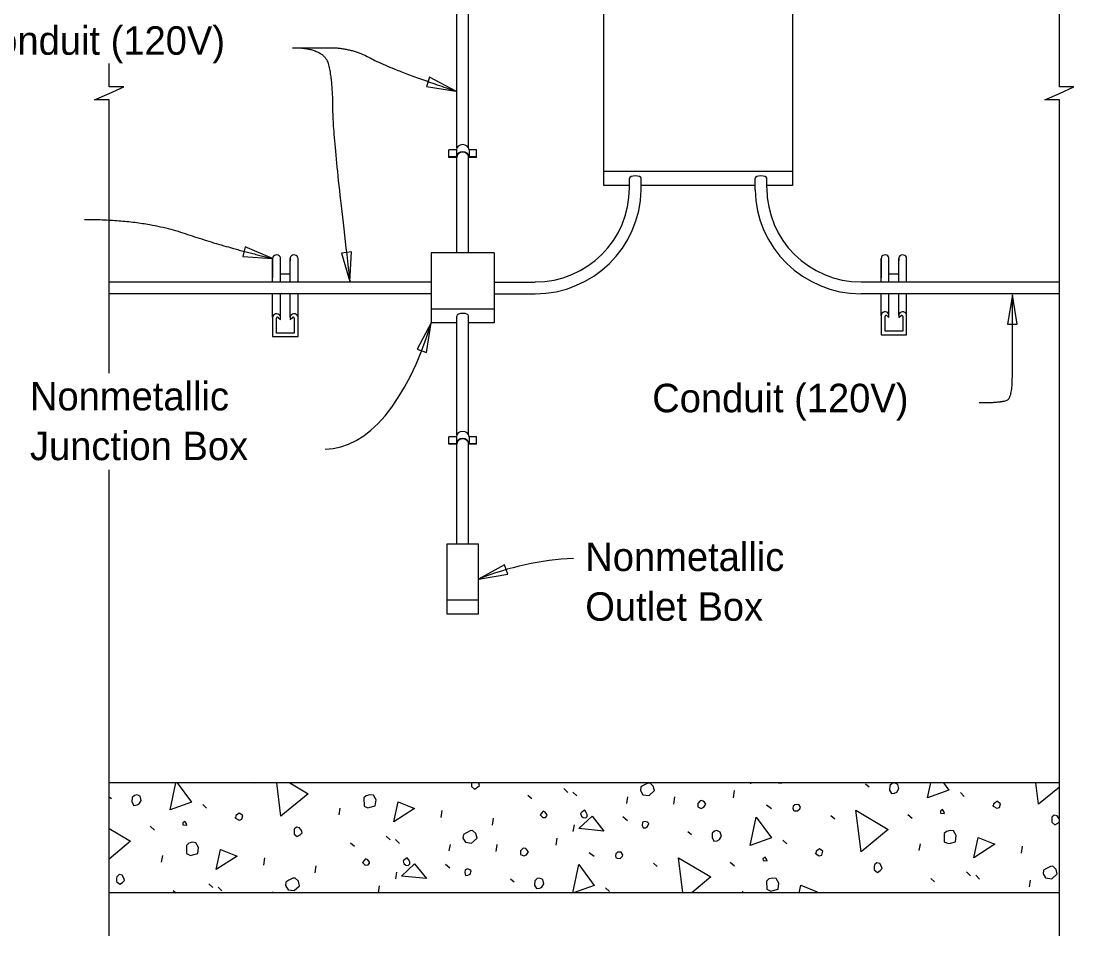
# Model space of a CAD drawing. Extents: x 112544 to 112597.1, y 111084 to 111107.1.
# Drawn here: x 112556.46 to 112562.05, y 111095.87 to 111100.72 of the extents above; entities that cross this region are included whole.
import ezdxf

# ---------------------------------------------------------------- set-up
doc = ezdxf.new("R2010")
doc.units = 0
for name, color, linetype in [('Dimension', 7, 'Continuous'), ('Lighting', 7, 'Continuous'), ('Miscellaneous', 7, 'Continuous'), ('SteelGirder', 7, 'Continuous'), ('SupstrConc', 7, 'Continuous'), ('TextStructures', 7, 'Continuous')]:
    doc.layers.add(name, color=color, linetype=linetype)

msp = doc.modelspace()

# ---------------------------------------------------------------- linework, layer by layer
at = {"layer": 'Dimension'}
for points in [[(112561.9699, 111095.8655), (112561.9699, 111100.3037), (112561.8924, 111100.3037), (112561.9699, 111100.3375), (112562.0474, 111100.3712), (112561.9699, 111100.3712), (112561.9699, 111101.4759)], [(112556.9271, 111098.8519), (112556.9271, 111100.3037), (112556.8496, 111100.3037), (112556.9271, 111100.3375), (112557.0046, 111100.3712), (112556.9271, 111100.3712), (112556.9271, 111100.4962)], [(112556.9271, 111095.8655), (112556.9271, 111098.3401)]]:
    msp.add_lwpolyline(points, dxfattribs=at)
for points in [[(112558.7675, 111100.3488), (112558.628, 111100.424), (112558.6111, 111100.3738)], [(112557.7946, 111099.4611), (112557.6487, 111099.5227), (112557.6365, 111099.4712)], [(112558.2053, 111099.3383), (112558.2127, 111099.4965), (112558.1602, 111099.4901)], [(112561.7205, 111099.2686), (112561.694, 111099.1124), (112561.7469, 111099.1124)], [(112558.637, 111099.1186), (112558.5614, 111098.9794), (112558.6114, 111098.9623)], [(112558.8871, 111097.7595), (112559.0433, 111097.7855), (112559.0261, 111097.8356)]]:
    msp.add_lwpolyline(points, close=True, dxfattribs=at)
msp.add_arc((112559.4765, 111096.2657), 1.606, 93.0575, 111.5329, dxfattribs=at)
msp.add_ellipse((112558.0721, 111100.0271), major_axis=(-0.0019, 1.5782), ratio=0.437101, start_param=3.141566, end_param=4.098452, dxfattribs=at)
for points in [[(112557.9001, 111100.5798), (112557.9837, 111100.5798), (112558.2136, 111100.5798), (112558.4185, 111100.4669), (112558.7675, 111100.3488)], [(112557.9001, 111100.5798), (112558.0715, 111100.5798), (112558.1133, 111100.3959), (112558.1133, 111100.0949), (112558.2053, 111099.3383)], [(112556.7965, 111099.6685), (112557.1101, 111099.6685), (112557.549, 111099.5191), (112557.7946, 111099.4611)], [(112561.5444, 111098.6959), (112561.6709, 111098.6959), (112561.7205, 111098.7257), (112561.7205, 111098.9513), (112561.7205, 111099.2686)]]:
    msp.add_open_spline(points, degree=2, dxfattribs=at)
at = {"layer": 'Lighting'}
for p, q in [((112558.7725, 111100.0474), (112558.7725, 111100.811)), ((112558.8349, 111100.0474), (112558.8349, 111100.811)), ((112558.7725, 111099.4913), (112558.7725, 111099.9976)), ((112558.8349, 111099.4913), (112558.8349, 111099.9976)), ((112560.5529, 111099.9227), (112559.5529, 111099.9227)), ((112559.6884, 111099.8362), (112559.6884, 111099.8856)), ((112559.7508, 111099.8256), (112559.7508, 111099.8856)), ((112560.355, 111099.8256), (112560.355, 111099.8856)), ((112560.4174, 111099.8362), (112560.4174, 111099.8856)), ((112558.637, 111099.4913), (112558.637, 111099.1186)), ((112558.9704, 111099.4913), (112558.637, 111099.4913)), ((112558.9704, 111099.4913), (112558.9704, 111099.1186)), ((112557.7946, 111099.3361), (112557.7946, 111099.4611)), ((112557.7946, 111099.4611), (112557.7946, 111099.3586)), ((112557.8362, 111099.4655), (112557.8341, 111099.4693)), ((112557.8362, 111099.4494), (112557.8362, 111099.4655)), ((112557.8362, 111099.3361), (112557.8362, 111099.4611)), ((112557.8905, 111099.4693), (112557.8884, 111099.4655)), ((112557.8884, 111099.4655), (112557.8884, 111099.4494)), ((112557.8884, 111099.3361), (112557.8884, 111099.4611)), ((112557.93, 111099.3361), (112557.93, 111099.4611)), ((112561.0242, 111099.3361), (112561.0242, 111099.4611)), ((112561.0242, 111099.4611), (112561.0242, 111099.3586)), ((112561.0658, 111099.4655), (112561.0636, 111099.4693)), ((112561.0658, 111099.4494), (112561.0658, 111099.4655)), ((112561.0658, 111099.3361), (112561.0658, 111099.4611)), ((112561.1201, 111099.4693), (112561.118, 111099.4655)), ((112561.118, 111099.4655), (112561.118, 111099.4494)), ((112561.118, 111099.3361), (112561.118, 111099.4611)), ((112561.1596, 111099.3361), (112561.1596, 111099.4611)), ((112557.8884, 111099.3772), (112557.8362, 111099.3772)), ((112561.118, 111099.3772), (112561.0658, 111099.3772)), ((112558.637, 111099.3361), (112556.9271, 111099.3361)), ((112558.9704, 111099.3361), (112559.1884, 111099.3361)), ((112561.9699, 111099.3361), (112560.9174, 111099.3361)), ((112558.637, 111099.2737), (112556.9271, 111099.2737)), ((112557.7946, 111099.1487), (112557.7946, 111099.2737)), ((112557.8362, 111099.1487), (112557.8362, 111099.2737)), ((112557.8884, 111099.1487), (112557.8884, 111099.2737)), ((112557.93, 111099.1487), (112557.93, 111099.2737)), ((112558.9704, 111099.2737), (112559.1884, 111099.2737)), ((112561.9699, 111099.2737), (112560.9174, 111099.2737)), ((112561.0242, 111099.159), (112561.0242, 111099.2737)), ((112561.0658, 111099.159), (112561.0658, 111099.2737)), ((112561.118, 111099.159), (112561.118, 111099.2737)), ((112561.1596, 111099.159), (112561.1596, 111099.2737)), ((112557.7946, 111099.1487), (112557.7946, 111099.0462)), ((112557.8154, 111099.0648), (112557.8154, 111099.1444)), ((112557.8243, 111099.1477), (112557.8362, 111099.137)), ((112557.8362, 111099.1531), (112557.8341, 111099.1569)), ((112557.8362, 111099.137), (112557.8362, 111099.1531)), ((112557.8905, 111099.1569), (112557.8884, 111099.1531)), ((112557.8884, 111099.1531), (112557.8884, 111099.137)), ((112557.8884, 111099.137), (112557.9003, 111099.1477)), ((112557.9092, 111099.1444), (112557.9092, 111099.0648)), ((112557.93, 111099.0462), (112557.93, 111099.1487)), ((112558.9704, 111099.1928), (112558.637, 111099.1928)), ((112558.7725, 111098.5253), (112558.7725, 111099.1557)), ((112558.8349, 111098.5253), (112558.8349, 111099.1557)), ((112561.0242, 111099.159), (112561.0242, 111099.0565)), ((112561.045, 111099.0751), (112561.045, 111099.1547)), ((112561.0539, 111099.158), (112561.0658, 111099.1473)), ((112561.0658, 111099.1634), (112561.0636, 111099.1672)), ((112561.0658, 111099.1473), (112561.0658, 111099.1634)), ((112561.1201, 111099.1672), (112561.118, 111099.1634)), ((112561.118, 111099.1634), (112561.118, 111099.1473)), ((112561.118, 111099.1473), (112561.1299, 111099.158)), ((112561.1388, 111099.1547), (112561.1388, 111099.0751)), ((112561.1596, 111099.0565), (112561.1596, 111099.159)), ((112558.7725, 111099.1186), (112558.637, 111099.1186)), ((112558.9704, 111099.1186), (112558.8349, 111099.1186)), ((112557.7946, 111099.0462), (112557.93, 111099.0462)), ((112557.9092, 111099.0648), (112557.8154, 111099.0648)), ((112561.0242, 111099.0565), (112561.1596, 111099.0565)), ((112561.1388, 111099.0751), (112561.045, 111099.0751)), ((112558.7725, 111097.9459), (112558.7725, 111098.4755)), ((112558.8349, 111097.9459), (112558.8349, 111098.4755)), ((112558.7204, 111097.5733), (112558.7204, 111097.9459)), ((112558.7204, 111097.9459), (112558.887, 111097.9459)), ((112558.887, 111097.5733), (112558.887, 111097.9459)), ((112558.887, 111097.6476), (112558.7204, 111097.6476)), ((112558.887, 111097.5733), (112558.7204, 111097.5733))]:
    msp.add_line(p, q, dxfattribs=at)
for points in [[(112559.6884, 111099.8484), (112559.5529, 111099.8484), (112559.5529, 111102.5734), (112560.5529, 111102.5734), (112560.5529, 111099.8484), (112560.4174, 111099.8484)], [(112560.355, 111099.8484), (112559.7507, 111099.8484)]]:
    msp.add_lwpolyline(points, dxfattribs=at)
for centre, radius, start, end in [((112559.1884, 111099.8362), 0.5, 270, 0), ((112559.1884, 111099.8362), 0.5625, 270, 358.9196), ((112560.9174, 111099.8362), 0.5625, 181.0804, 270), ((112560.9174, 111099.8362), 0.5, 180, 270)]:
    msp.add_arc(centre, radius, start, end, dxfattribs=at)
for centre, major_axis, ratio, start_param, end_param in [((112559.7196, 111099.8856), (-0.0312, 0), 0.446008, 3.14248, 6.283159), ((112560.3862, 111099.8856), (-0.0312, 0), 0.446008, 3.141619, 6.282298), ((112557.8154, 111099.4611), (-0.0208, 0), 0.8951, 3.598509, 6.283184), ((112557.9092, 111099.4611), (0.0208, 0), 0.8951, 0.000002, 2.684677), ((112561.045, 111099.4611), (-0.0208, 0), 0.8951, 3.598509, 6.283184), ((112561.1388, 111099.4611), (0.0208, 0), 0.8951, 0.000002, 2.684677), ((112557.8154, 111099.1487), (-0.0208, 0), 0.8951, 3.598509, 6.283184), ((112557.8206, 111099.1444), (-0.0052, 0), 0.8951, 3.926991, 6.283185), ((112557.9092, 111099.1487), (0.0208, 0), 0.8951, 0.000002, 2.684677), ((112557.904, 111099.1444), (0.0052, 0), 0.8951, 6.283185, 8.63938), ((112558.8037, 111099.1557), (-0.0312, 0), 0.446008, 3.14248, 6.283159), ((112561.045, 111099.159), (-0.0208, 0), 0.8951, 3.598509, 6.283184), ((112561.0502, 111099.1547), (-0.0052, 0), 0.8951, 3.926991, 6.283185), ((112561.1388, 111099.159), (0.0208, 0), 0.8951, 0.000002, 2.684677), ((112561.1336, 111099.1547), (0.0052, 0), 0.8951, 6.283185, 8.63938)]:
    msp.add_ellipse(centre, major_axis=major_axis, ratio=ratio, start_param=start_param, end_param=end_param, dxfattribs=at)
at = {"layer": 'Miscellaneous'}
for p, q in [((112557.6971, 111096.6779), (112557.6991, 111096.6762)), ((112559.3399, 111096.6474), (112559.3609, 111096.6272)), ((112559.3887, 111096.6294), (112559.4097, 111096.6092)), ((112560.2407, 111096.5989), (112560.2461, 111096.6366)), ((112560.3322, 111096.6726), (112560.3331, 111096.6779)), ((112560.9405, 111096.6725), (112560.9601, 111096.6571)), ((112556.9271, 111096.6039), (112556.9394, 111096.5943)), ((112559.1501, 111096.6121), (112559.1704, 111096.5942)), ((112559.6742, 111096.5688), (112559.6803, 111096.604)), ((112559.9235, 111096.5657), (112559.9289, 111096.6034)), ((112561.4446, 111096.6264), (112561.4655, 111096.6062)), ((112557.4238, 111096.5636), (112557.4448, 111096.5434)), ((112558.1476, 111096.5091), (112558.1537, 111096.5444)), ((112558.69, 111096.494), (112558.6954, 111096.5317)), ((112560.4166, 111096.5606), (112560.4424, 111096.5417)), ((112558.9624, 111096.4531), (112558.9678, 111096.4908)), ((112559.6541, 111096.4987), (112559.6775, 111096.4791)), ((112560.7577, 111096.5045), (112560.778, 111096.4867)), ((112561.1652, 111096.5101), (112561.1885, 111096.4905)), ((112557.1444, 111096.4474), (112557.1678, 111096.4277)), ((112559.3904, 111096.4203), (112559.3965, 111096.4555)), ((112559.9987, 111096.4202), (112560.0184, 111096.4047)), ((112558.2083, 111096.3597), (112558.2286, 111096.3419)), ((112558.3982, 111096.3951), (112558.4191, 111096.3748)), ((112558.447, 111096.3771), (112558.4679, 111096.3568)), ((112558.7324, 111096.3164), (112558.7385, 111096.3517)), ((112558.9817, 111096.3133), (112558.9871, 111096.351)), ((112559.2989, 111096.3466), (112559.3043, 111096.3842)), ((112560.5028, 111096.3741), (112560.5238, 111096.3538)), ((112561.2266, 111096.3196), (112561.2327, 111096.3548)), ((112557.2058, 111096.2568), (112557.2119, 111096.292)), ((112559.4748, 111096.3083), (112559.5006, 111096.2893)), ((112561.769, 111096.3044), (112561.7744, 111096.3421)), ((112557.7482, 111096.2416), (112557.7536, 111096.2793)), ((112558.0206, 111096.2007), (112558.026, 111096.2384)), ((112558.7124, 111096.2463), (112558.7357, 111096.2267)), ((112559.816, 111096.2522), (112559.8363, 111096.2343)), ((112560.2234, 111096.2578), (112560.2467, 111096.2382)), ((112558.4487, 111096.1679), (112558.4547, 111096.2032)), ((112561.4771, 111096.2055), (112561.4981, 111096.1852)), ((112561.5259, 111096.1875), (112561.5469, 111096.1673)), ((112557.4564, 111096.1427), (112557.4773, 111096.1225)), ((112557.5052, 111096.1247), (112557.5261, 111096.1045)), ((112558.3572, 111096.0946), (112558.3626, 111096.1319)), ((112559.0569, 111096.1678), (112559.0766, 111096.1524)), ((112561.2873, 111096.1702), (112561.3076, 111096.1523)), ((112561.8114, 111096.1268), (112561.8175, 111096.1621)), ((112557.2666, 111096.1074), (112557.2811, 111096.0946)), ((112557.7959, 111096.0946), (112557.7967, 111096.0993)), ((112558.0448, 111096.0946), (112558.0453, 111096.0987)), ((112559.561, 111096.1217), (112559.582, 111096.1015)), ((112560.2895, 111096.0946), (112560.2909, 111096.1025))]:
    msp.add_line(p, q, dxfattribs=at)
for points in [[(112557.2503, 111096.5353), (112557.2805, 111096.6779)], [(112557.2884, 111096.6779), (112557.3636, 111096.576), (112557.2503, 111096.5353)], [(112557.8391, 111096.5015), (112557.8167, 111096.6779)], [(112557.8855, 111096.6779), (112557.9832, 111096.6204), (112557.8391, 111096.5015)], [(112558.8507, 111096.6768), (112558.8504, 111096.6586), (112558.867, 111096.6449), (112558.8826, 111096.6543), (112558.8927, 111096.6648), (112558.8895, 111096.6768), (112558.8888, 111096.6779)], [(112558.8507, 111096.6779), (112558.8507, 111096.6768)], [(112559.7464, 111096.6373), (112559.7601, 111096.6151), (112559.7923, 111096.6108), (112559.8216, 111096.6367), (112559.8151, 111096.6609), (112559.7979, 111096.677), (112559.7852, 111096.6761), (112559.7647, 111096.6655), (112559.7491, 111096.6561), (112559.7464, 111096.6373)], [(112560.4922, 111096.6779), (112560.4947, 111096.6747), (112560.4632, 111096.6779)], [(112561.0698, 111096.6632), (112561.0684, 111096.6395), (112561.0784, 111096.6215), (112561.0959, 111096.6236), (112561.1074, 111096.6292), (112561.118, 111096.6476), (112561.1121, 111096.6694), (112561.0944, 111096.6775), (112561.0823, 111096.6743), (112561.0698, 111096.6632)], [(112561.271, 111096.598), (112561.288, 111096.6779)], [(112561.3554, 111096.6779), (112561.3843, 111096.6388), (112561.271, 111096.598)], [(112561.8598, 111096.5643), (112561.8454, 111096.6779)], [(112561.9699, 111096.655), (112561.8598, 111096.5643)], [(112557.049, 111096.6004), (112557.0476, 111096.5767), (112557.0576, 111096.5587), (112557.0752, 111096.5608), (112557.0866, 111096.5665), (112557.0972, 111096.5848), (112557.0914, 111096.6066), (112557.0737, 111096.6148), (112557.0616, 111096.6115), (112557.049, 111096.6004)], [(112558.2789, 111096.5986), (112558.2802, 111096.555), (112558.301, 111096.545), (112558.3131, 111096.5483), (112558.3397, 111096.5554), (112558.344, 111096.5876), (112558.3296, 111096.6122), (112558.3108, 111096.615), (112558.2914, 111096.6098), (112558.2789, 111096.5986)], [(112558.4375, 111096.4703), (112558.4606, 111096.5774), (112558.5479, 111096.5413), (112558.4375, 111096.4703)], [(112560.052, 111096.569), (112560.0517, 111096.5508), (112560.0694, 111096.5427), (112560.0832, 111096.549), (112560.0945, 111096.5649), (112560.0864, 111096.5757), (112560.0797, 111096.5816), (112560.0687, 111096.5839), (112560.0639, 111096.5826), (112560.052, 111096.569)], [(112561.6192, 111096.5542), (112561.6376, 111096.5436), (112561.6521, 111096.5474), (112561.6572, 111096.5669), (112561.6382, 111096.58), (112561.6298, 111096.5725), (112561.6208, 111096.5675), (112561.6192, 111096.5542), (112561.6179, 111096.559)], [(112557.5985, 111096.4914), (112557.6168, 111096.4808), (112557.6313, 111096.4847), (112557.6365, 111096.5042), (112557.6174, 111096.5172), (112557.6091, 111096.5098), (112557.6001, 111096.5048), (112557.5985, 111096.4914), (112557.5972, 111096.4962)], [(112559.2143, 111096.5077), (112559.2285, 111096.4933), (112559.2436, 111096.4948), (112559.2514, 111096.5046), (112559.2501, 111096.5095), (112559.2414, 111096.5227), (112559.2298, 111096.5273), (112559.222, 111096.5175), (112559.2143, 111096.5077)], [(112559.4333, 111096.5016), (112559.4432, 111096.4939), (112559.4565, 111096.4923), (112559.4649, 111096.4997), (112559.4647, 111096.51), (112559.4591, 111096.5215), (112559.451, 111096.5323), (112559.4378, 111096.5235), (112559.4295, 111096.5161), (112559.4333, 111096.5016)], [(112560.5583, 111096.5339), (112560.5645, 111096.5304), (112560.5802, 111096.5294), (112560.5928, 111096.5405), (112560.5957, 111096.5491), (112560.587, 111096.5623), (112560.5663, 111096.5619), (112560.558, 111096.5545), (112560.5557, 111096.5436), (112560.5583, 111096.5339)], [(112560.918, 111096.3119), (112560.8901, 111096.5322), (112561.0622, 111096.4308), (112560.918, 111096.3119)], [(112561.3391, 111096.5179), (112561.3603, 111096.5159), (112561.3577, 111096.5255), (112561.3497, 111096.5363), (112561.3389, 111096.5282), (112561.3391, 111096.5179)], [(112557.3183, 111096.4551), (112557.3396, 111096.4531), (112557.337, 111096.4627), (112557.3289, 111096.4735), (112557.3181, 111096.4654), (112557.3183, 111096.4551)], [(112559.4199, 111096.4359), (112559.4904, 111096.5014), (112559.5529, 111096.4224), (112559.4199, 111096.4359)], [(112559.7568, 111096.4537), (112559.7607, 111096.4392), (112559.7734, 111096.44), (112559.7848, 111096.4457), (112559.7906, 111096.4628), (112559.7838, 111096.4687), (112559.7722, 111096.4734), (112559.7577, 111096.4695), (112559.7568, 111096.4537)], [(112560.3292, 111096.3457), (112560.3613, 111096.4966), (112560.4426, 111096.3864), (112560.3292, 111096.3457)], [(112561.9296, 111096.4872), (112561.9293, 111096.469), (112561.9459, 111096.4554), (112561.9615, 111096.4647), (112561.9699, 111096.4733)], [(112561.9699, 111096.482), (112561.9684, 111096.4873), (112561.9591, 111096.5029), (112561.9427, 111096.5062), (112561.9301, 111096.4951), (112561.9296, 111096.4872)], [(112556.9271, 111096.4354), (112557.0414, 111096.368), (112556.9271, 111096.2738)], [(112557.9089, 111096.4244), (112557.9086, 111096.4062), (112557.9252, 111096.3926), (112557.9408, 111096.4019), (112557.9509, 111096.4124), (112557.9477, 111096.4245), (112557.9383, 111096.4401), (112557.9219, 111096.4435), (112557.9094, 111096.4323), (112557.9089, 111096.4244)], [(112558.8046, 111096.3849), (112558.8183, 111096.3627), (112558.8506, 111096.3584), (112558.8798, 111096.3844), (112558.8734, 111096.4085), (112558.8561, 111096.4246), (112558.8434, 111096.4238), (112558.823, 111096.4131), (112558.8073, 111096.4038), (112558.8046, 111096.3849)], [(112560.128, 111096.4108), (112560.1266, 111096.3872), (112560.1366, 111096.3691), (112560.1542, 111096.3712), (112560.1656, 111096.3769), (112560.1762, 111096.3953), (112560.1704, 111096.417), (112560.1526, 111096.4252), (112560.1406, 111096.422), (112560.128, 111096.4108)], [(112561.3579, 111096.4091), (112561.3592, 111096.3654), (112561.38, 111096.3555), (112561.3921, 111096.3587), (112561.4186, 111096.3658), (112561.4229, 111096.3981), (112561.4086, 111096.4227), (112561.3897, 111096.4254), (112561.3704, 111096.4202), (112561.3579, 111096.4091)], [(112557.3371, 111096.3463), (112557.3385, 111096.3027), (112557.3592, 111096.2927), (112557.3713, 111096.2959), (112557.3979, 111096.3031), (112557.4022, 111096.3353), (112557.3878, 111096.3599), (112557.369, 111096.3626), (112557.3497, 111096.3574), (112557.3371, 111096.3463)], [(112561.5165, 111096.2808), (112561.5396, 111096.3879), (112561.6269, 111096.3518), (112561.5165, 111096.2808)], [(112557.4957, 111096.218), (112557.5188, 111096.3251), (112557.6061, 111096.289), (112557.4957, 111096.218)], [(112559.1102, 111096.3167), (112559.1099, 111096.2985), (112559.1276, 111096.2903), (112559.1415, 111096.2966), (112559.1527, 111096.3126), (112559.1447, 111096.3233), (112559.1379, 111096.3293), (112559.1269, 111096.3315), (112559.1221, 111096.3302), (112559.1102, 111096.3167)], [(112559.6165, 111096.2816), (112559.6227, 111096.278), (112559.6385, 111096.2771), (112559.651, 111096.2882), (112559.6539, 111096.2967), (112559.6452, 111096.3099), (112559.6246, 111096.3096), (112559.6162, 111096.3022), (112559.614, 111096.2912), (112559.6165, 111096.2816)], [(112560.6775, 111096.3018), (112560.6958, 111096.2912), (112560.7103, 111096.2951), (112560.7154, 111096.3146), (112560.6964, 111096.3276), (112560.6881, 111096.3202), (112560.679, 111096.3152), (112560.6775, 111096.3018), (112560.6762, 111096.3067)], [(112558.2725, 111096.2553), (112558.2867, 111096.241), (112558.3019, 111096.2425), (112558.3096, 111096.2523), (112558.3083, 111096.2571), (112558.2996, 111096.2703), (112558.288, 111096.275), (112558.2803, 111096.2651), (112558.2725, 111096.2553)], [(112558.4781, 111096.1836), (112558.5486, 111096.249), (112558.6112, 111096.17), (112558.4781, 111096.1836)], [(112558.4916, 111096.2493), (112558.5014, 111096.2416), (112558.5148, 111096.24), (112558.5231, 111096.2474), (112558.523, 111096.2577), (112558.5173, 111096.2691), (112558.5092, 111096.2799), (112558.4961, 111096.2712), (112558.4877, 111096.2638), (112558.4916, 111096.2493)], [(112559.3877, 111096.0946), (112559.4195, 111096.2443), (112559.5008, 111096.1341), (112559.3911, 111096.0946)], [(112559.9718, 111096.0946), (112559.9483, 111096.2799), (112560.1204, 111096.1784), (112560.0188, 111096.0946)], [(112560.3973, 111096.2656), (112560.4185, 111096.2635), (112560.416, 111096.2732), (112560.4079, 111096.2839), (112560.3971, 111096.2759), (112560.3973, 111096.2656)], [(112560.9879, 111096.2349), (112560.9876, 111096.2167), (112561.0042, 111096.203), (112561.0198, 111096.2124), (112561.0299, 111096.2229), (112561.0267, 111096.2349), (112561.0173, 111096.2505), (112561.0009, 111096.2539), (112560.9883, 111096.2428), (112560.9879, 111096.2349)], [(112556.9671, 111096.1721), (112556.9668, 111096.1539), (112556.9834, 111096.1402), (112556.999, 111096.1496), (112557.0091, 111096.1601), (112557.0059, 111096.1721), (112556.9966, 111096.1878), (112556.9801, 111096.1911), (112556.9676, 111096.18), (112556.9671, 111096.1721)], [(112558.815, 111096.2014), (112558.8189, 111096.1869), (112558.8316, 111096.1877), (112558.843, 111096.1933), (112558.8488, 111096.2104), (112558.842, 111096.2164), (112558.8304, 111096.221), (112558.8159, 111096.2171), (112558.815, 111096.2014)], [(112561.8836, 111096.1954), (112561.8973, 111096.1732), (112561.9295, 111096.1689), (112561.9588, 111096.1948), (112561.9523, 111096.219), (112561.9351, 111096.235), (112561.9224, 111096.2342), (112561.9019, 111096.2236), (112561.8863, 111096.2142), (112561.8836, 111096.1954)], [(112557.8628, 111096.1326), (112557.8766, 111096.1104), (112557.9088, 111096.1061), (112557.9381, 111096.132), (112557.9316, 111096.1562), (112557.9143, 111096.1723), (112557.9016, 111096.1714), (112557.8812, 111096.1608), (112557.8656, 111096.1514), (112557.8628, 111096.1326)], [(112559.1862, 111096.1585), (112559.1848, 111096.1348), (112559.1948, 111096.1168), (112559.2124, 111096.1189), (112559.2238, 111096.1246), (112559.2344, 111096.1429), (112559.2286, 111096.1647), (112559.2109, 111096.1728), (112559.1988, 111096.1696), (112559.1862, 111096.1585)], [(112560.4161, 111096.1567), (112560.4174, 111096.1131), (112560.4382, 111096.1031), (112560.4503, 111096.1064), (112560.4769, 111096.1135), (112560.4812, 111096.1457), (112560.4668, 111096.1703), (112560.448, 111096.173), (112560.4286, 111096.1679), (112560.4161, 111096.1567)], [(112560.589, 111096.0946), (112560.5978, 111096.1355), (112560.6851, 111096.0994), (112560.6777, 111096.0946)]]:
    msp.add_lwpolyline(points, dxfattribs=at)
at = {"layer": 'SteelGirder'}
for p, q in [((112558.7702, 111100.0373), (112558.7308, 111100.0373)), ((112558.7308, 111099.9976), (112558.7308, 111100.0373)), ((112558.7702, 111100.0373), (112558.7702, 111100)), ((112558.8766, 111100.0373), (112558.8372, 111100.0373)), ((112558.8372, 111100.0373), (112558.8372, 111100)), ((112558.8766, 111099.9976), (112558.8766, 111100.0373)), ((112558.7702, 111100), (112558.7308, 111100)), ((112558.7725, 111099.9976), (112558.7308, 111099.9976)), ((112558.8766, 111099.9976), (112558.8349, 111099.9976)), ((112558.8766, 111100), (112558.8372, 111100)), ((112558.7702, 111098.5152), (112558.7308, 111098.5152)), ((112558.7308, 111098.4755), (112558.7308, 111098.5152)), ((112558.7702, 111098.4778), (112558.7308, 111098.4778)), ((112558.7725, 111098.4755), (112558.7308, 111098.4755)), ((112558.7702, 111098.5152), (112558.7702, 111098.4778)), ((112558.8766, 111098.4755), (112558.8349, 111098.4755)), ((112558.8766, 111098.5152), (112558.8372, 111098.5152)), ((112558.8372, 111098.5152), (112558.8372, 111098.4778)), ((112558.8766, 111098.4778), (112558.8372, 111098.4778)), ((112558.8766, 111098.4755), (112558.8766, 111098.5152))]:
    msp.add_line(p, q, dxfattribs=at)
for centre, major_axis, ratio, end_param in [((112558.8037, 111100.0373), (-0.0335, 0), 0.830773, 6.282753), ((112558.8037, 111100), (-0.0335, 0), 0.830773, 6.282753), ((112558.8037, 111099.9976), (-0.0312, 0), 0.892016, 6.283768), ((112558.8037, 111098.5152), (-0.0335, 0), 0.830773, 6.282753), ((112558.8037, 111098.4778), (-0.0335, 0), 0.830773, 6.282753), ((112558.8037, 111098.4755), (-0.0312, 0), 0.892016, 6.283768)]:
    msp.add_ellipse(centre, major_axis=major_axis, ratio=ratio, start_param=3.141593, end_param=end_param, dxfattribs=at)
at = {"layer": 'SupstrConc'}
for p, q in [((112561.9699, 111096.6779), (112556.9271, 111096.6779)), ((112561.9699, 111096.0946), (112556.9271, 111096.0946))]:
    msp.add_line(p, q, dxfattribs=at)

# ---------------------------------------------------------------- texts
at = {"layer": 'Dimension'}
for s, p in [('Nonmetallic', (112556.5071, 111098.6547)), ('Junction Box', (112556.5071, 111098.3907))]:
    msp.add_text(s, height=0.1512, dxfattribs=at).set_placement(p)
at = {"layer": 'TextStructures'}
for s, p in [('Conduit (120V)', (112556.1823, 111100.5422)), ('Conduit (120V)', (112559.8093, 111098.6449)), ('Nonmetallic ', (112559.454, 111097.8023)), ('Outlet Box', (112559.454, 111097.5383))]:
    msp.add_text(s, height=0.1512, dxfattribs=at).set_placement(p)

doc.saveas('drawing.dxf')
